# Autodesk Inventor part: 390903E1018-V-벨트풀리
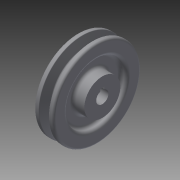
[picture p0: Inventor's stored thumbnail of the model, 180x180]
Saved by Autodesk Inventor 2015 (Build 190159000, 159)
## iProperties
Created: 2019-09
Part Number: 390903E1018-V-벨트풀리
Material: 일반
Document SubType Name: Modeling
Designer: now015
Density: 1 g/cm^3
Appearance: 기본값
Author: now015
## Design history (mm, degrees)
sketch "스케치1"
  geometry: C1 r 42.5 at (0, 0); 1 further point
  constraints: 1 centre point, 1 coincident
  dimensions: "d0" = 85 diameter of C1
extrude "돌출1" new body sketch "스케치1" stored distance "d1" = 19; taper "d2" = 0 deg
sketch "스케치2"
  geometry: L1 (9.5, 42.5)-(9.5, -42.5) reference; L2 (9.5, -42.5)-(-9.5, -42.5) reference; L3 (-9.5, -42.5)-(-9.5, 42.5) reference; L4 (-9.5, 42.5)-(9.5, 42.5) reference; L5 (4.877, 42.5)-(1.953, 33.5); L6 (1.953, 33.5)-(-1.953, 33.5); L7 (-1.953, 33.5)-(-4.877, 42.5); L8 (4, 39.8)-(-4, 39.8); L9 (-9.5, 42.5)-(-9.5, -42.5) reference; L10 (0, 42.5)-(0, 33.5); L11 (13.3, 0)-(-13.3, 0) reference; 1 further point
  constraints: 10 end point, 4 point on line, 2 midpoint, 1 horizontal, 1 perpendicular, 1 vertical, 1 other
  dimensions: "d3" = 36 deg angle of L7 L5; "d4" = 2.7 distance between parallel lines of L8 L4; "d5" = 6.3 distance between parallel lines of L6 L8; "d6" = 9.5 distance between parallel lines of L10 L1 (derived); "d7" = 8 distance of L8.end L8.start
revolve "회전1" sketch "스케치2" stored, may be unused: angle "d8" = 90 deg
sketch "스케치3"
  geometry: C1 r 42.5 at (0, 0) reference; C2 r 29 at (0, 0); C3 r 17.5 at (0, 0)
  constraints: 2 centre point, 2 coincident
  dimensions: "d9" = 58 diameter of C2; "d10" = 35 diameter of C3
extrude "돌출2" cut sketch "스케치3" distance "d11" = 6; taper "d12" = 0 deg
sketch "스케치4"
  geometry: C1 r 29 at (0, 0) reference; C2 r 29 at (0, 0); C3 r 17.5 at (0, 0)
  constraints: 2 centre point, 2 coincident
  dimensions: "d13" = 58 diameter of C2; "d14" = 35 diameter of C3
extrude "돌출3" cut sketch "스케치4" distance "d15" = 6; taper "d16" = 0 deg
fillet "모깎기1" dims "d17" = 3
fillet "모깎기2" dims "d18" = 3
fillet "모깎기3" dims "d19" = 3
fillet "모깎기4" dims "d20" = 3
sketch "스케치5"
  geometry: C1 r 17.5 at (0, 0) reference
extrude "돌출4" join sketch "스케치5" distance "d21" = 5; taper "d22" = 0 deg
sketch "스케치6"
  geometry: C1 r 26 at (0, 0) reference; C2 r 6 at (0, 0)
  constraints: 1 centre point, 1 coincident
  dimensions: "d23" = 12 diameter of C2
extrude "돌출5" cut sketch "스케치6" stored distance "d24" = 5; taper "d25" = 0 deg
sketch "스케치7"
  geometry: L1 (-7.8, -2)-(0, -2); L2 (0, -2)-(0, 2); L3 (0, 2)-(-7.8, 2); L4 (-7.8, 2)-(-7.8, -2); C1 r 6 at (0, 0) reference; 1 further point
  constraints: 8 end point, 2 parallel, 1 coincident, 1 horizontal, 1 midpoint, 1 perpendicular
  dimensions: "d26" = 4 distance of L3.end L1.start; "d27" = 13.8 dimension on C1 L4
extrude "돌출6" cut sketch "스케치7" stored distance "d28" = 5; taper "d29" = 0 deg
fillet "모깎기5" dims "d30" = 2
fillet "모깎기6" dims "d31" = 0.5
fillet "모깎기7" dims "d32" = 1
node "솔리드1"
node "절단 모서리 투영1"
